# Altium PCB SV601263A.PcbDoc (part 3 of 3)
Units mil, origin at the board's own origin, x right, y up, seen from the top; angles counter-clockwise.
Board outline 4070 x 6530 mil, 6 copper layers (Top Layer, Signal Layer 1, Signal Layer 2, Signal Layer 3, Signal Layer 4, Bottom Layer), stack 60.36 mil thick; 305 components, 177 nets, 942 pads, 354 vias.
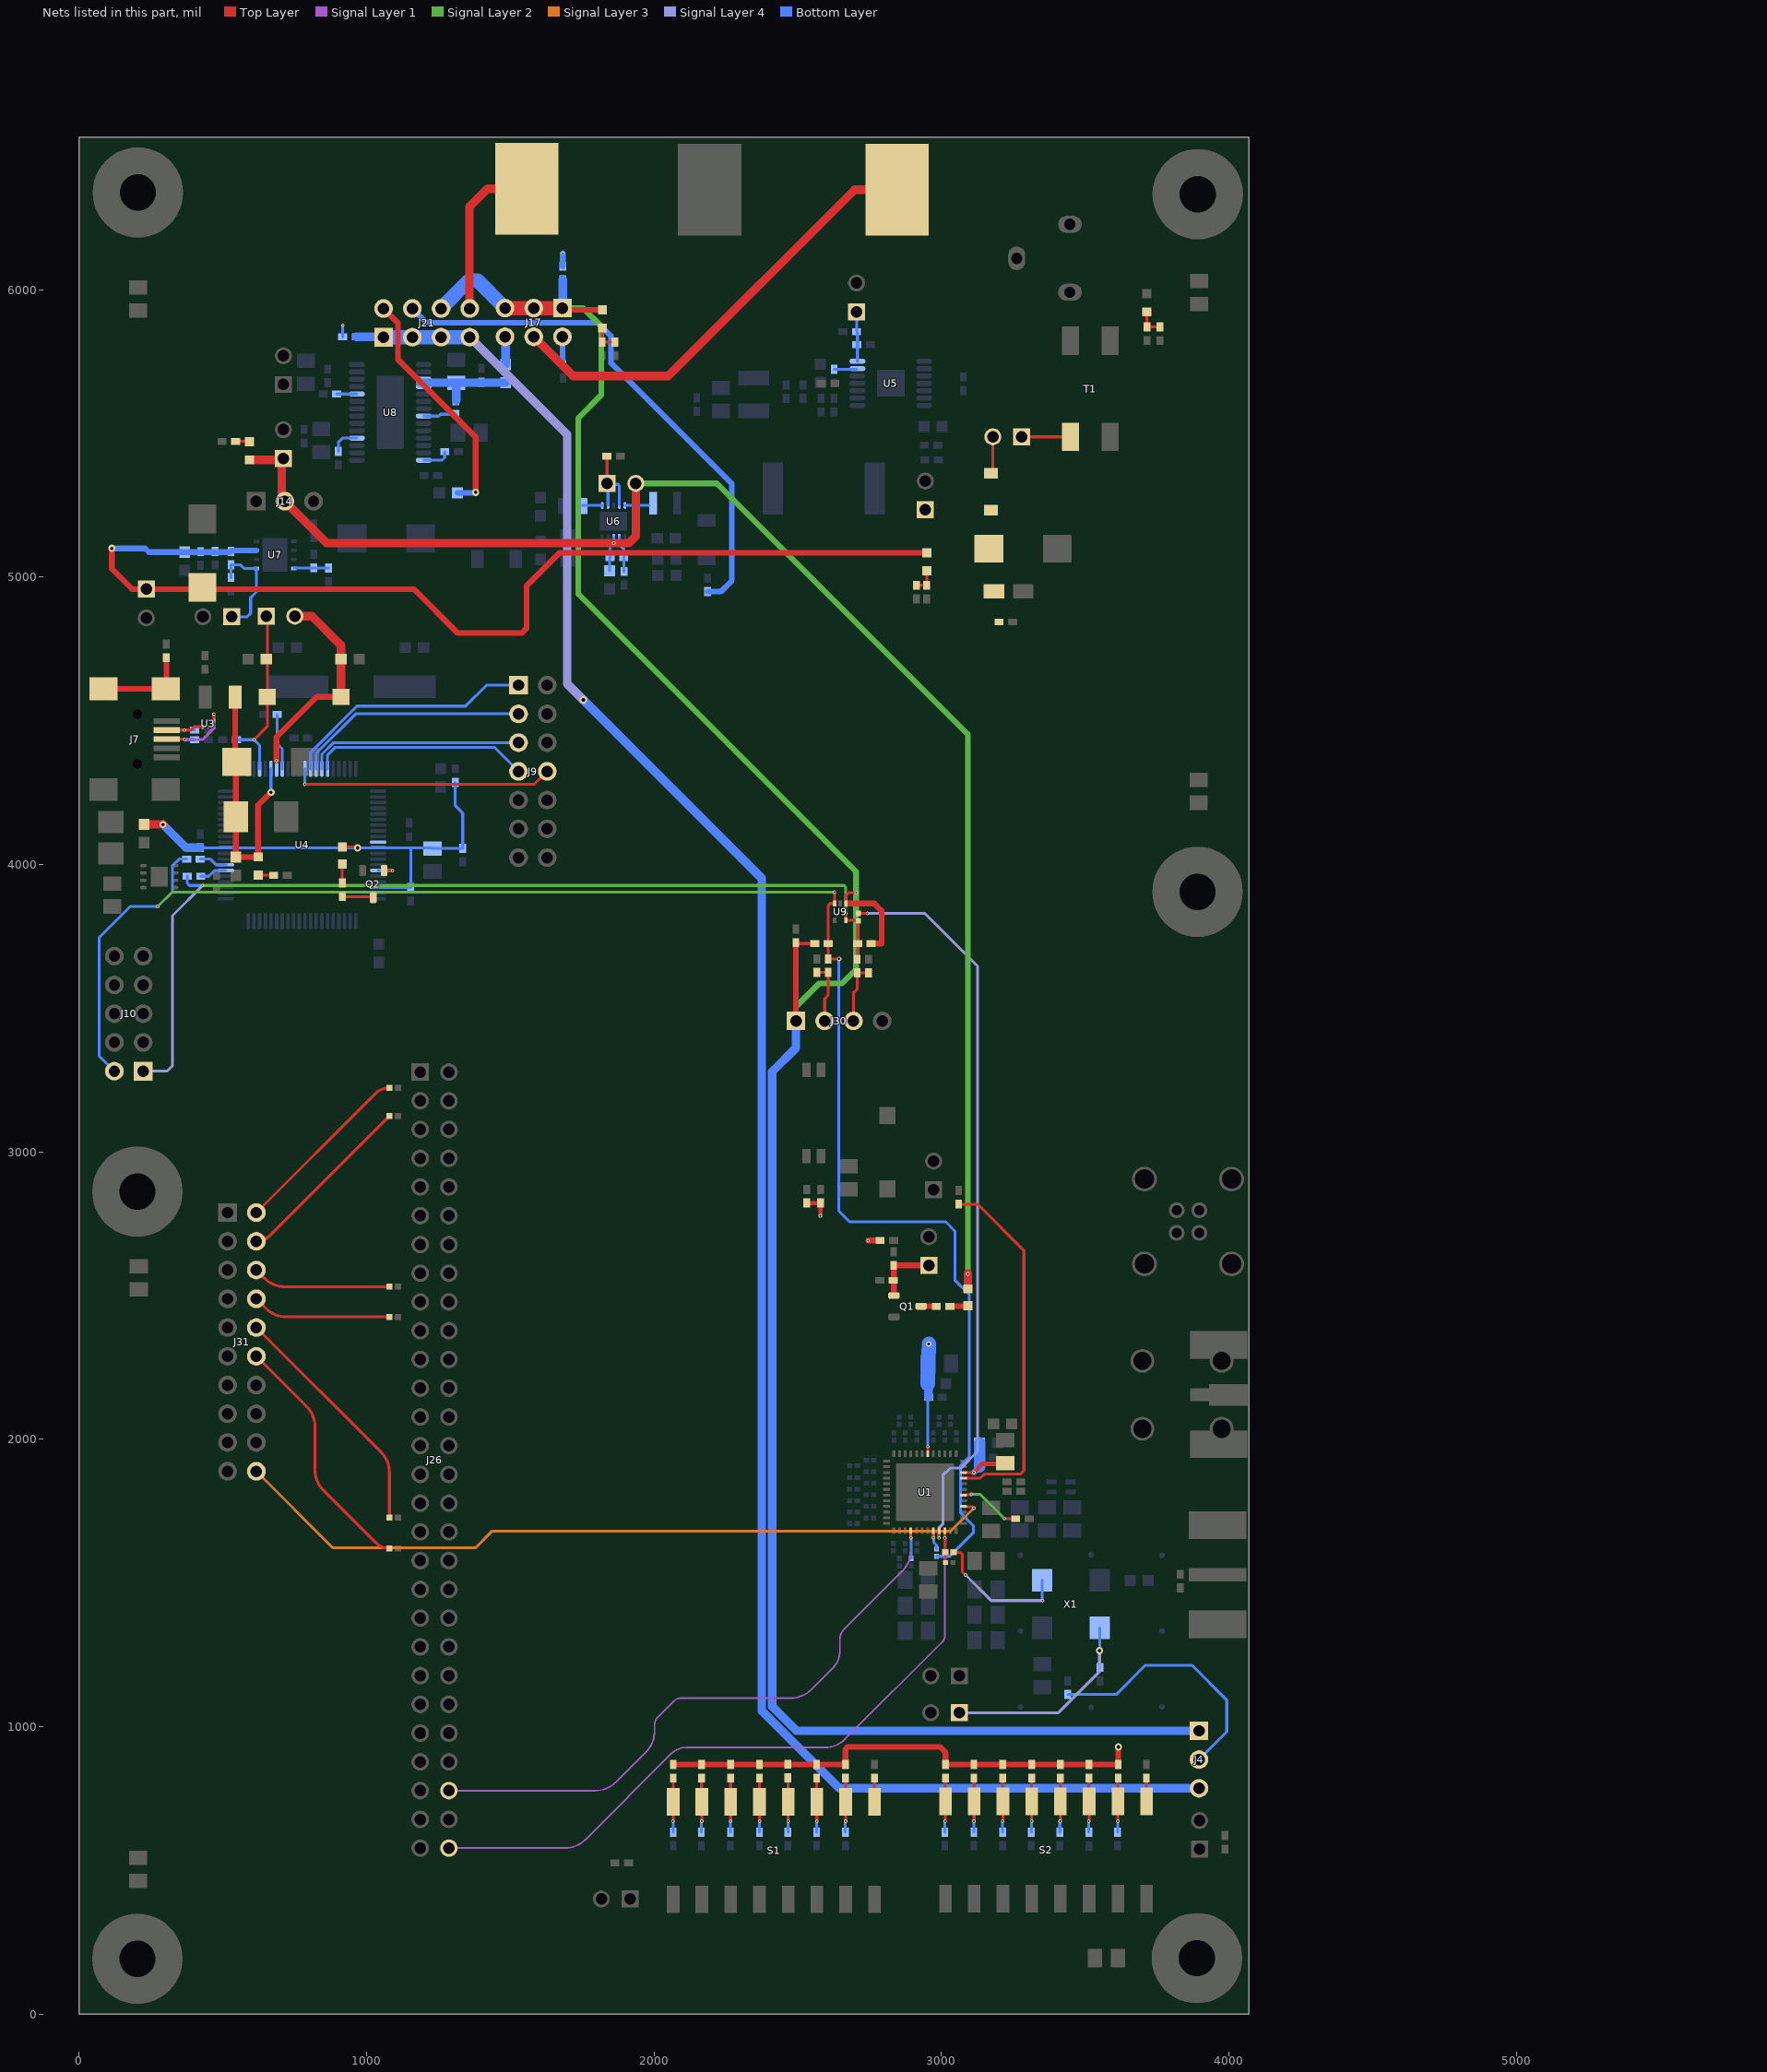
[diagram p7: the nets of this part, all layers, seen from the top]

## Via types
v1: diameter 15, hole 7.5, Top Layer to Bottom Layer, 187 vias
v2: diameter 12, hole 6, Top Layer to Bottom Layer, 96 vias
v3: diameter 19.68, hole 7.87, Top Layer to Bottom Layer, 28 vias
v4: diameter 15.75, hole 7.87, Top Layer to Bottom Layer, 18 vias
v5: diameter 20, hole 10, Top Layer to Bottom Layer, 14 vias
v6: diameter 25, hole 12, Top Layer to Bottom Layer, 9 vias
v7: diameter 16, hole 8, Top Layer to Bottom Layer, 2 vias

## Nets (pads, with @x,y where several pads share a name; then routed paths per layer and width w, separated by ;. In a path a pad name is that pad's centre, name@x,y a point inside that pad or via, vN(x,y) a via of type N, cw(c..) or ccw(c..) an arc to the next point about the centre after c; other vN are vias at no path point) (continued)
NetC78_2: C78.2 C79.1 R112.2 R114.1 U8.17 U8.18 | length 357.9
  Bottom Layer w30: 1187.5,5676.5 R114.1@1484,5676.5 ; R112.2@1312,5614.62 C79.1@1312,5676
NetC85_1: C85.1 J30.2 R118.2 | length 212.3
  Top Layer w10: C85.1@2567,3624.38 R118.2@2606,3624.38 2606,3545 2594,3533 J30.2@2594,3456
NetC86_1: C86.1 J30.3 R119.2 | length 212.8
  Top Layer w10: J30.3@2694,3456 2694,3553 2707,3566 R119.2@2707,3623.38 C86.1@2747,3623.38
NetD1_1: D1.1 R70.2 R75.2 | length 96.9
  Top Layer w10: D1.1@3715,5922.5 R75.2@3715,5870.62 R70.2@3760,5870.62
NetD2_1: D2.1 R71.2 R76.2 | length 85.9
  Top Layer w10: R76.2@2913,4971.62 R71.2@2949,4971.62 D2.1@2949,5021.5
NetD3_1: D3.1 R72.2 | length 52.9
  Top Layer w10: D3.1@623,3963.5 R72.2@675.87,3963.5
NetD4_1: D4.1 R73.2 | length 46.9
  Top Layer w10: R73.2@544.62,5472 D4.1@591.5,5472
NetD5_1: D5.1 R74.2 R77.2 | length 93.3
  Top Layer w10: D5.1@1821,5866.5 1820,5865.5 R74.2@1820,5817.62 R77.2@1864,5817.62
NetD6_2: D6.2 R69.2 | length 60.9
  Top Layer w20: R69.2@3029.62,2463 D6.2@3090.53,2463
NetD8_2: D8.2 R87.2 | length 65.9
  Top Layer w10: R87.2@916,3935.62 D8.2@916,4001.47
NetD9_2: D9.2 J12.2 | length 120.5
  Top Layer w10: D9.2@3179,5367.47 J12.2@3179,5488
NetJ4_2: J4.2 L1.2 | length 892.4
  Bottom Layer w10: L1.2@3440,1112.38 3607.38,1112.38 3709,1214 3872,1214 3993,1093 3993,983 J4.2@3896,886
NetJ6_1: J6.1 R33.1 X1.1 | length 755.9
  Signal Layer 4 w10: J6.1@3063,1049 3407,1049 3550,1192 v6(3550,1265)
  Bottom Layer w10: R33.1@3551,1207.62 X1.1@3551,1344.32
NetJ7_2: J7.2 R80.2 U3.1 | length 164.7
  Top Layer w10: J7.2@305.36,4467.5 v2(367,4467.5) 389.5,4467.5 401.17,4479.17 U3.1@430.31,4479.17
  Bottom Layer w10: v2@367.5,4468 R80.2@402.38,4468
NetJ7_3: J7.3 R81.2 U3.4 | length 281.7
  Top Layer w10: J7.3@305.36,4436 v2@367,4436 ; U3.4@469.68,4501.81 v2@469.68,4522.31
  Signal Layer 1 w10: v2(368,4435) 430,4435 469,4474 v2(469,4523)
  Bottom Layer w10: v2@369,4434 R81.2@402.38,4434
NetJ7_8: J7.8 J7.9 R83.2 | length 325.8
  Top Layer w20: J7.8@84.89,4611.2 J7.9@301.43,4611.2 304,4613.77 R83.2@304,4719.38
NetJ9_1: J9.1 U4.72 | length 877.4
  Bottom Layer w10: U4.72@805.53,4332.76 805.53,4389.53 967,4551 1345,4551 1418,4624 J9.1@1529,4624
NetJ9_3: J9.3 U4.73 | length 814.5
  Bottom Layer w10: U4.73@825.21,4332.76 825.21,4386.59 962.63,4524 J9.3@1529,4524
NetJ9_5: J9.5 U4.74 | length 751.7
  Bottom Layer w10: U4.74@844.9,4332.76 844.9,4383.64 885.25,4424 J9.5@1529,4424
NetJ9_7: J9.7 U4.75 | length 758.5
  Bottom Layer w10: U4.75@864.58,4332.76 864.58,4380.7 891.88,4408 1445,4408 J9.7@1529,4324
NetJ9_8: J9.8 U4.71 | length 915.6
  Top Layer w10: v2(785,4279) 1584,4279 J9.8@1629,4324
  Bottom Layer w10: v2@785.84,4279.84 U4.71@785.84,4332.76
NetJ12_1: J12.1 T1.3 | length 169.8
  Top Layer w10: J12.1@3279,5488 T1.3@3448.78,5488
NetJ15_1: J15.1 R93.2 R95.2 U5.7 | length 168.6
  Bottom Layer w10: R95.2@2705,5854.38 J15.1@2705,5923 ; U5.7@2707.86,5750.77 R95.2@2707.86,5850.76
NetJ16_1: J16.1 R97.2 U6.7 U6.9 | length 277.3
  Top Layer w10: J16.1@1837,5326 R97.2@1837,5419.38
  Bottom Layer w10: U6.7@1840.32,5249.12 1840.32,5322.69 1875.32,5322.69 1879.69,5318.31 U6.9@1879.69,5249.12
NetJ19_1: J19.1 R103.1 R108.2 U7.1 | length 372.1
  Bottom Layer w10: R108.2@529,4998.62 R103.1@529,5042.38 561.62,5042.38 574.24,5029.76 U7.1@617.04,5029.76 617.04,4948.04 597,4928 597,4874 585,4862 J19.1@531,4862
NetJ31_2: J31.2 R121.1 | length 639.8
  Top Layer w10: J31.2@617,2789 1030.47,3202.47 cw(c1080.04,3152.89) R121.1@1080.04,3223
NetJ31_4: J31.4 R122.1 | length 640.8
  Top Layer w10: J31.4@617,2689 ccw(c617,2754.28) 663.16,2708.12 R122.1@1080.04,3125
NetJ31_6: J31.6 R123.1 | length 482.8
  Top Layer w10: J31.6@617,2589 645.71,2560.29 ccw(c716.42,2631) 716.42,2531 R123.1@1080.04,2531
NetJ31_8: J31.8 R124.1 | length 484.8
  Top Layer w10: J31.8@617,2489 650.71,2455.29 ccw(c721.42,2526) 721.42,2426 R124.1@1080.04,2426
NetJ31_10: J31.10 R125.1 | length 848.5
  Top Layer w10: J31.10@617,2389 1050.75,1955.25 cw(c980.04,1884.54) 1080.04,1884.54 R125.1@1080.04,1728
NetJ31_12: J31.12 R126.1 | length 864.7
  Top Layer w10: J31.12@617,2289 791.71,2114.29 cw(c721,2043.58) 821,2043.58 821,1893.42 ccw(c921,1893.42) 850.29,1822.71 1032.17,1640.83 ccw(c1080.04,1688.69) R126.1@1080.04,1621
NetJ32_1: J32.1 Q1.1 R53.2 R78.2 | length 225.8
  Top Layer w20: R53.2@2834,2605.38 J32.1@2955.62,2605.38 ; Q1.1@2834.76,2500.4 R53.2@2834.76,2604.62
NetL8_1: L8.1 U6.6 | length 69.2
  Bottom Layer w10: L8.1@1751.46,5249.12 U6.6@1820.63,5249.12
NetL10_1: L10.1 U6.10 | length 83.2
  Bottom Layer w10: U6.10@1899.37,5249.12 1982.54,5249.12
NetQ1_3: Q1.3 R69.1 | length 53.1
  Top Layer w20: Q1.3@2929.24,2463 R69.1@2982.38,2463
NetQ2_1: Q2.1 U4.15 | length 77.2
  Top Layer w10: Q2.1@1061.4,3979.24 v2@1089.76,3979.24
  Bottom Layer w10: U4.15@1040.76,3979.42 v2@1089.58,3979.42
  other v2: 1091,3978
NetQ2_3: Q2.3 R87.1 | length 104.4
  Top Layer w10: R87.1@916,3888.38 Q2.3@1020.38,3888.38
NetR1_1: R1.1 R15.2 S1.16 | length 185.8
  Top Layer w10: v2@2067,673 S1.16@2067,738.29 R1.1@2067,821.38
  Bottom Layer w10: R15.2@2067,633.62 v2@2067,671
  other v2: 2066,672
NetR2_1: R2.1 R16.2 S1.15 | length 184.8
  Top Layer w10: S1.15@2166,739.29 R2.1@2166,821.38 ; v2(2167,672) S1.15@2167,738.29
  Bottom Layer w10: R16.2@2165,633.62 v2@2165,670
NetR3_1: R3.1 R17.2 S1.14 | length 188.2
  Top Layer w10: v2(2267,672) S1.14@2267,738.29 R3.1@2267,821.38
  Bottom Layer w10: v2@2266,671 R17.2@2266,633.62 R17.2@2267,634.62
NetR4_1: R4.1 R18.2 S1.13 | length 185.8
  Top Layer w10: v2@2367,673 S1.13@2367,738.29 R4.1@2367,821.38
  Bottom Layer w10: R18.2@2367,633.62 v2@2367,671
  other v2: 2368,672
NetR5_1: R5.1 R19.2 S1.12 | length 186.8
  Top Layer w10: v2(2467,672) S1.12@2467,738.29 R5.1@2467,821.38
  Bottom Layer w10: R19.2@2466,633.62 v2@2466,671
NetR6_1: R6.1 R20.2 S1.11 | length 185.8
  Top Layer w10: S1.11@2566,739.29 R6.1@2566,821.38 ; v2(2567,672) S1.11@2567,738.29
  Bottom Layer w10: R20.2@2566,633.62 v2@2566,671
NetR7_1: R7.1 R21.2 S1.10 | length 185.8
  Top Layer w10: v2(2667,672) S1.10@2667,738.29 R7.1@2667,820.38
  Bottom Layer w10: R21.2@2666,633.62 v2@2666,671
NetR8_1: R8.1 R23.2 S2.16 | length 185.8
  Top Layer w10: v2@3014,673 S2.16@3014,740.29 R8.1@3014,821.38
  Bottom Layer w10: R23.2@3012,633.62 v2@3012,671
  other v2: 3013,672
NetR9_1: R9.1 R24.2 S2.15 | length 185.8
  Top Layer w10: v2@3114,673 S2.15@3114,740.29 R9.1@3114,820.38
  Bottom Layer w10: R24.2@3113,633.62 v2(3113,672)
NetR10_1: R10.1 R25.2 S2.14 | length 185.8
  Top Layer w10: S2.14@3213,741.29 R10.1@3213,821.38 ; v2@3214,673 S2.14@3214,740.29
  Bottom Layer w10: R25.2@3213,633.62 v2(3213,672)
NetR11_1: R11.1 R26.2 S2.13 | length 186.8
  Top Layer w10: v2(3314,672) S2.13@3314,740.29 R11.1@3314,821.38
  Bottom Layer w10: R26.2@3313,633.62 v2@3313,671
NetR12_1: R12.1 R27.2 S2.12 | length 185.8
  Top Layer w10: v2@3414,673 S2.12@3414,740.29 R12.1@3414,821.38
  Bottom Layer w10: R27.2@3412,633.62 v2@3412,671
  other v2: 3413,672
NetR13_1: R13.1 R28.2 S2.11 | length 186.8
  Top Layer w10: S2.11@3513,741.29 R13.1@3513,821.38 ; v2@3514,673 S2.11@3514,740.29
  Bottom Layer w10: R28.2@3513,632.62 v2(3513,672)
NetR14_1: R14.1 R29.2 S2.10 | length 185.8
  Top Layer w10: v2(3614,672) S2.10@3614,740.29 R14.1@3614,820.38
  Bottom Layer w10: R29.2@3613,633.62 v2@3613,671
NetR22_2: R22.2 S1.9 | length 83.1
  Top Layer w10: S1.9@2767,738.29 R22.2@2767,821.38
NetR30_2: R30.2 S2.9 | length 80.1
  Top Layer w10: S2.9@3713,741.29 R30.2@3713,821.38
NetR34_1: R34.1 X1.3 | length 484
  Top Layer w10: R34.1@3042.96,1607 3066,1607 3073,1600 3073,1539 v2(3084,1528)
  Signal Layer 4 w10: v2(3084,1528) 3173,1439 v2(3352,1439)
  Bottom Layer w10: v2@3351,1440 X1.3@3351,1509.68
NetR88_2: R88.2 U4.47 | length 97.9
  Bottom Layer w10: R88.2@421.62,4019 457,4019 476.9,3999.1 U4.47@511.24,3999.1
NetR89_1: R89.1 U4.46 | length 96.1
  Bottom Layer w10: R89.1@423.62,3959 452,3959 472.42,3979.42 U4.46@511.24,3979.42
NetR92_1: R92.1 U5.6 | length 78.3
  Bottom Layer w10: R92.1@2627,5722.62 U5.6@2705.3,5722.62
NetR100_1: R100.1 R102.2 U6.2 | length 126
  Bottom Layer w10: U6.2@1879.69,5138.88 1879.69,5112.31 1896,5096 R102.2@1896,5019.62
NetR106_1: R106.1 R107.2 U7.8 | length 119.2
  Bottom Layer w10: U7.8@748.83,5031.62 R107.2@868,5031.62
NetR109_2: R109.2 U8.28 | length 96.9
  Bottom Layer w10: U8.28@1199.14,5406.66 1262.66,5406.66 1272.38,5416.38 R109.2@1272.38,5436
NetR110_2: R110.2 U8.4 | length 102.2
  Bottom Layer w10: R110.2@902,5437.62 902,5469 916.43,5483.43 U8.4@966.86,5483.43
NetR112_1: R112.1 U8.22 | length 114.4
  Bottom Layer w10: U8.22@1199.14,5560.2 1251.2,5560.2 1257.38,5566.38 R112.1@1311,5566.38
NetR113_2: R113.2 U8.10 | length 70.2
  Bottom Layer w10: R113.2@896.62,5637 U8.10@966.86,5636.98
NetU4_10: U4.10
PCLK: J26.56 R34.2 R65.1 U1.10 | length 2475.7
  Top Layer w10: v2@3011.9,1657.1 U1.10@3011.9,1682.14 ; v2@3013.04,1655.96 R34.2@3013.04,1607 3013.04,1573.34 ccw(c3016.35,1573.34) R65.1@3014.01,1571
  Signal Layer 1 w6: J26.56@1287,578 1690.58,578 ccw(c1690.58,678) 1761.29,607.29 2060,906 cw(c2113.11,852.89) 2113.11,928 2594.58,928 ccw(c2594.58,1028) 2665.29,957.29 3002,1294 ccw(c2977.86,1318.14) 3012,1318.14 v2(3012,1657)
PDB_R: R64.1 U1.21 | length 1280.7
  Top Layer w10: R64.1@3060,2818.38 3125.62,2818.38 3287,2657 3287,1891 3275,1879 3149,1879 3135.21,1865.21 U1.21@3076.86,1865.21
PUR: J8.1 R82.1 R84.2 S5.1 U4.63 | length 615.7
  Top Layer w10: v2(609,4434) 655.05,4480.05 S5.1@655.05,4583 J8.1@655.05,4859.95
  Bottom Layer w10: R82.1@547.62,4434 v2(609,4434) 628.36,4414.64 U4.63@628.36,4332.76
REM_INTB: J31.20 U1.16 | length 2702.7
  Top Layer w10: U1.16@3076.86,1766.79 3076.86,1765.47 3108.53,1765.47 v2(3113,1761)
  Signal Layer 3 w10: J31.20@617,1889 883,1623 1380,1623 1438,1681 3033,1681 v2(3113,1761)
RES1: R56.1 U1.18 | length 215.1
  Top Layer w10: U1.18@3076.86,1806.16 3076.86,1807.47 v2@3102.47,1807.47 ; v2@3220,1724 R56.1@3258.38,1724
  Signal Layer 2 w10: v2(3104,1809) 3135,1809 v2(3219,1725)
SCL: J10.2 R39.2 R88.1 R116.1 R118.1 U9.3 | length 6192.6
  Top Layer w10: R118.1@2606,3671.62 v7@2643.78,3671.62 ; R118.1@2606.62,3672.24 R116.1@2606.62,3725 2606.62,3857.62 2613.53,3864.53 U9.3@2628.32,3864.53 v2@2628.32,3903.69
  Signal Layer 2 w10: v2(274,3854) 324,3904 v2(2628,3904)
  Bottom Layer w10: J10.2@123,3281 70,3334 70,3746 178,3854 v2(274,3854) 325,3905 325,3996 348,4019 R88.1@374.38,4019 ; v7@2643,3672 2643,2795 2681,2757 3015,2757 3047,2725 3047,2554 3097,2504 3097,1940 3067,1910 3067,1744 3111,1700 3111,1675 3029.01,1593.01 R39.2@2983,1593.01
  other v7: 2644.16,3672
SCL_R: R39.1 U1.8 | length 65.8
  Top Layer w10: v2@2972.53,1658.53 U1.8@2972.53,1682.14
  Bottom Layer w10: v2@2973,1657 2973,1642 2983,1632 R39.1@2983,1618.99
  other v2: 2972,1658
SDA: J10.1 R37.2 R89.2 R115.1 R119.1 U9.5 | length 3387.6
  Top Layer w10: v2@2667.69,3829.31 U9.5@2667.69,3805.47 2704.29,3805.47 2708.38,3801.39 R115.1@2708.38,3725 R119.1@2708.38,3672
  Signal Layer 2 w10: v2(430,3927) 2661,3927 2667,3921 v2(2667,3830)
  Signal Layer 4 w10: J10.1@223,3281 306,3281 325,3300 325,3822 v2(430,3927)
  Bottom Layer w10: R89.2@376.38,3959 376.38,3934.62 384,3927 v2(430,3927)
SDA_R: R37.1 U1.9 | length 2582.9
  Top Layer w10: R37.1@2711,3829.99 v2(2743,3830) ; v2@2992.21,1657.21 U1.9@2992.21,1682.14
  Signal Layer 4 w10: v2(2743,3830) 2942,3830 3126,3646 3126,1958 3068,1900 3030,1900 3005,1875 3005,1706 2992,1693 v2(2992,1657)
V18: C22.1 U4.67 | length 196.5
  Bottom Layer w10: C22.1@689.62,4522 689.62,4420.38 707.1,4402.9 U4.67@707.1,4332.76
VBUS: C14.1 D3.2 D7.1 F1.1 L2.1 U4.65 | length 959.2
  Top Layer w20: F1.1@543.36,4583 543.36,4362.54 545.99,4359.91 D7.1@545.99,4166 L2.1@546,4025.5 D3.2@622.01,4025.5 ; D3.2@623,4026.5 623,4206 v6(668,4251)
  Bottom Layer w10: v6@667.73,4251.27 U4.65@667.73,4332.76
VDD1V8_LDO: J21.2 R111.2 | length 835.9
  Top Layer w20: J21.2@1058,5936 1109.52,5884.48 1109.52,5757.48 1380,5487 v6(1380,5295)
  Bottom Layer w20: R111.2@1316.5,5293 v6@1378,5293
VDD5V: C59.2 D4.2 D6.1 J14.2 J16.2 J22.1 R100.2 U6.3 | length 5287.7
  Top Layer w30: D4.2@593,5407.5 705.5,5407.5 J14.2@705.5,5274.5 ; J14.2@716,5264 862,5118 v2(1860,5118) 1912,5118 1937,5143 J16.2@1937,5326 ; D6.1@3092,2523.53 v2(3092,2576)
  Signal Layer 2 w20: J16.2@1937,5326 2219,5326 3092,4453 v2(3092,2576)
  Bottom Layer w10: C59.2@1846,5021.5 R100.2@1846,5065.62 ; R100.2@1847.38,5067 1847.38,5105.38 v2(1860,5118) U6.3@1860,5138.88
VDD18_SW: J21.4 R99.2 | length 1857.6
  Bottom Layer w20: J21.4@1158,5936 1209.52,5884.48 1804.52,5884.48 1851,5838 1851,5744 2271,5324 2271,4988 2232.38,4949.38 R99.2@2187,4949.38
VDD33: C83.2 D5.2 J4.1 J17.1 J17.3 J17.5 J21.6 J30.1 L7.1 R115.2 R116.2 U9.1 | length 8502.1
  Top Layer w10: C83.2@2497.38,3725 R116.2@2559.38,3725 ; U9.1@2667.69,3864.53 2667.69,3891.69 2678,3902 v2(2704,3902)
  Top Layer w20: J17.1@1688.5,5929.5 D5.2@1821,5929.5 ; J30.1@2494,3456 C83.2@2494,3728.38 ; U9.1@2669.91,3864.53 2766.47,3864.53 2792,3839 2792,3725 R115.2@2755.62,3725
  Top Layer w50: J17.5@1482,5936 J17.3@1582,5936 J17.1@1682,5936
  Signal Layer 2 w20: J17.1@1682,5936 1754,5936 1817,5873 1817,5634 1737,5554 1737,4941 2703,3975 2703,3635 2654,3586 2574,3586 2494,3506 J30.1@2494,3456
  Bottom Layer w30: J17.1@1683,5937 L7.1@1683,6034.38 ; J30.1@2494,3456 2494,3362 2411,3279 2411,1070.91 2495.91,986 J4.1@3896,986
  Bottom Layer w50: J21.6@1259.52,5934.48 1357.04,6032 1386,6032 J17.5@1482,5936
VDD33_C: C54.1 C55.1 C56.1 L7.2 R1.2 R2.2 R3.2 R4.2 R5.2 R6.2 R7.2 R8.2 R9.2 R10.2 R11.2 R12.2 R13.2 R14.2 R31.2 R32.2 U1.22 | length 2118.3
  Top Layer w10: U1.22@3076.86,1884.9 v2@3112.9,1884.9
  Top Layer w15: R32.2@2532,2822.38 R31.2@2580,2822.38 v2@2580,2779 ; v2(3113,1885) 3143,1915 3220,1915 C56.1@3222,1917
  Top Layer w20: R1.2@2067,868.62 R2.2@2166,868.62 R3.2@2267,868.62 R4.2@2367,868.62 R6.2@2566,868.62 R7.2@2666,868.62 2666,922 2674,930 2995,930 3014,911 R8.2@3014,868.62 R9.2@3113,868.62 R10.2@3213,868.62 R11.2@3314,868.62 R12.2@3414,868.62 R13.2@3513,868.62 R14.2@3615,868.62 v6@3615,929
  Bottom Layer w20: L7.2@1683,6081.62 v2(1683,6126) ; v2(3113,1885) 3131,1903
  Bottom Layer w40: 3132.5,1904.5 C55.1@3132.5,1988
  other v2: 2579,2778
  other v6: 3616,930
VDD33_EXT: J17.4 J23.1 | length 1585.9
  Top Layer w30: J17.4@1584,5834 1718,5700 2050,5700 2698,6348 J23.1@2846,6348
VDD33_LDO: J17.6 R114.2 | length 94.5
  Bottom Layer w30: R114.2@1484,5739.5 J17.6@1484,5834
VDD33_SW: J17.2 R94.2 | length 94.4
  Bottom Layer w20: R94.2@1682,5741.62 J17.2@1682,5836
VDD33_UC: C25.1 C26.1 C27.2 C28.1 D8.1 R79.2 R86.1 U4.11 U4.18 U4.50 | length 1674.6
  Top Layer w10: D8.1@916,4060.53 v6@966.63,4060.53
  Top Layer w30: R79.2@227,4139.5 v6@291.5,4139.5
  Bottom Layer w10: C25.1@422.22,4058.16 U4.50@511.24,4058.16 v6(969,4058.16) U4.11@1040.76,4058.16 C26.1@1227.84,4058.16 ; U4.18@1040.76,3920.36 C28.1@1153.74,3920.36 ; C28.1@1154,3920.62 1154,4057.16 ; C26.1@1230,4056 C27.2@1331.38,4056 ; R86.1@1309,4285.38 1309,4205 1335,4179 C27.2@1335,4056.62
  Bottom Layer w30: v6(292,4139) 372.62,4058.38 C25.1@422,4058.38
VDD_EXT: C43.2 C44.1 C45.1 C67.1 C68.1 C69.1 C70.1 D2.2 D9.1 J11.1 J18.1 R103.2 U7.3 | length 3712.5
  Top Layer w20: v6(114,5100) 114,5029 185,4958 1165,4958 1318,4805 1540,4805 1557,4822 1557,4970 1671.5,5084.5 D2.2@2949,5084.5
  Bottom Layer w20: v6(114,5100) 230.09,5100 243.6,5086.5 C68.1@368,5086.5 525.87,5086.5 R103.2@529,5089.62 532.13,5092.75 U7.3@617.04,5092.75
VDDIO: J4.3 J21.1 J21.3 J21.5 J21.7 L9.1 | length 7225.3
  Signal Layer 4 w30: J21.7@1359.52,5834.48 1698,5496 1698,4629 v6(1754,4573)
  Bottom Layer w30: L9.1@964.62,5836 J21.1@1058,5836 ; v6(1754,4573) 2375,3952 2375,1056 2645,786 J4.3@3896,786
  Bottom Layer w50: J21.1@1059.52,5834.48 J21.3@1159.52,5834.48 J21.5@1259.52,5834.48 J21.7@1359.52,5834.48
VDDIO_C: C62.1 C63.1 C64.1 L9.2 R48.2 U1.30 | length 457.7
  Top Layer w10: v2@2952.73,1975.27 v2(2953,1975) ; U1.30@2952.84,1949.86 v2@2952.84,1974.84
  Top Layer w20: v2@2746,2692 R48.2@2786.38,2692
  Bottom Layer w10: L9.2@917.38,5836 v2@917.38,5875.38 ; v2(2953,1975) 2952.73,1975.27 2952.73,2036.87 2953,2037.14 C64.1@2953,2143.62 ; C63.1@2953,2183 C63.1@2953.38,2183.38
  Bottom Layer w30: C64.1@2955.38,2146 C63.1@2955.38,2191.13
  Bottom Layer w50: C63.1@2952.5,2194 2954.28,2263.99 v5(2956,2332)
  other v2: 2745,2691 918,5876
VDDIO_EXT: J21.8 J25.1 | length 578.1
  Top Layer w30: J21.8@1358,5936 1358,6288 1421,6351 J25.1@1558,6351
VS: J26.52 R67.1 U1.4 | length 2195.2
  Top Layer w10: v2@2893.79,1658.21 U1.4@2893.79,1682.14
  Signal Layer 1 w6: J26.52@1287,778 1796.58,778 ccw(c1796.58,878) 1867.29,807.29 1972.71,912.71 ccw(c1902,983.42) 2002,983.42 2002,1008 cw(c2035.8,1008) 2011.9,1031.9 2069,1089 cw(c2095.56,1062.44) 2095.56,1100 2476.58,1100 ccw(c2476.58,1200) 2547.29,1129.29 2622,1204 ccw(c2561.64,1264.36) 2647,1264.36 2647,1305 cw(c2695.28,1305) 2661.14,1339.14 2864.71,1542.71 ccw(c2794,1613.42) 2894,1613.42 v2(2894,1658)
  Bottom Layer w10: v2(2894,1658) cw(c2891.59,1655.59) 2895,1655.59 R67.1@2895,1585.99
VUSB: C20.2 J8.2 S5.2 U4.66 | length 745.8
  Top Layer w20: v2(687,4361) 687,4443 827,4583 S5.2@910.95,4583
  Top Layer w30: J8.2@751,4864 810,4864 910.95,4763.05 S5.2@910.95,4583
pads on no net: J7.4 J7.6 J7.7 J7.10 J7.11 J9.2 J9.4 J9.6 J9.10 J9.12 J9.13 J9.14 J10.3 J10.6 LBL?.0 SH-J11.0 SH-J12.0 SH-J19.0 SH-J22.0 U2.2 U2.6 U2.7 U3.2 U3.5 U4.1 U4.2 U4.3 U4.4 U4.5 U4.6 U4.7 U4.8 U4.12 U4.13 U4.16 U4.17 U4.21 U4.22 U4.24 U4.25 U4.26 U4.27 U4.28 U4.30 U4.31 U4.32 U4.34 U4.35 U4.36 U4.37 U4.38 U4.39 U4.40 U4.41 U4.42 U4.43 U4.44 U4.45 U4.48 U4.53 U4.54 U4.55 U4.56 U4.57 U4.58 U4.59 U4.60 U4.77 U4.78 U4.79 U4.80 U7.4 U7.6 U8.1 U8.2 U8.7 U8.8 U8.13 U8.14 U8.15 U8.16 U8.19 U8.20 U8.21 U8.25 U8.26 U8.27 U9.2

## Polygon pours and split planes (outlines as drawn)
VDD33_C on Signal Layer 2 "Signal Layer 2-VDD33_C" (solid, pour order 11): 0,0 4070,0 4070,6530 0,6530
GND on Signal Layer 3 "Signal Layer 3-GND" (solid, pour order 13): 0,0 4070,0 4070,6530 0,6530
VDD_EXT on Top Layer "Top Layer-VDD_EXT" (solid, pour order 10): 2911,5265 3218,5265 3218,4833 3217,4834 2995,4834 2995,5068 2994,5069 2911,5069 2911,5265
GND on Top Layer "Top Layer-GND" (solid, remove dead copper, pour order 19): 0,0 4070,0 4070,6530 0,6530
GND on Signal Layer 1 "Signal Layer 1-GND" (solid, remove dead copper, pour order 12): 0,0 4070,0 4070,6530 0,6530
VDDIO_C on Signal Layer 4 "Signal Layer 4-VDDIO_C" (solid, remove dead copper, pour order 14): 0,0 4070,0 4070,6530 0,6530
GND on Bottom Layer "Bottom Layer-GND" (solid, remove dead copper, pour order 15): 0,0 4070,0 4070,6530 0,6530

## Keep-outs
Keep-Out Layer:
  lines w10: -5,6528 -5,0 ; 0,6528 4075,6528 4075,6 4069,0 ; 4070,-5 0,-5 ; -5,0 ccw(c0,0) 0,-5 ; -5,0 ccw(c0,0) 0,-5 ; -5,3450 cw(c0,3450) 0,3455 ccw(c0,3450) -5,3450 ; 4950,3455 cw(c4950,3450) 4955,3450 ccw(c4950,3450) 4950,3455
  text ".Layer_Name" at 577,-858.49 h60

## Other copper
Top Layer:
  text ".Layer_Name" at 577,-858.49 h60
Bottom Layer:
  pour cut-out: 3410.25,1870.59 3421.75,1870.59 3422,1870.34 3422,1865 3410,1865
  pour cut-out: 2142.5,5094.72 2225.5,5094.72 2225.5,5109.5 2226,5110 2142,5110 2142,5095.23
  pour cut-out: 2036.44,5321.37 2036.44,5192.63 2041.56,5192.63 2041.56,5321.37
  pour cut-out: 2119.18,5176.88 2236,5177.06 2236,5110.03 2127.5,5109.72 2127.5,5093.1 2121.18,5093.1 2121.18,5105.7 2119.18,5105.7
  text ".Layer_Name" at 577,-858.49 h60

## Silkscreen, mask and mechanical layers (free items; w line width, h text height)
Top Overlay:
  region: 581,1229 281,1229 281,1129 581,1129
  lines w4: 271,5023 271,5155 ; 561,4794 585,4770 873,4770 911,4808 ; 911,4808 911,5098 1067,5098 1067,4808 911,4808
  text "VDDIO EXT" at 914,6321 h60
  text "3V3 EXT" at 2322,6320 h60
  text "GND" at 1876,6307 h60
  text "1V8 SW" at 1180,6029 h60 r90
  text "1V8 LDO" at 1075,6027 h60 r90
  text "VDDIO EXT" at 1370,6024 h60 r90
  text "VDD33" at 1282,6023 h60 r90
  text "VDD33" at 1424,6019 h60
  text "GND" at 2798,6001 h60
  text "VDD3V3" at 1842,5978 h60 r90
  text "GND" at 641,5956 h60
  text "12V ADPTR" at 3810,5908 h60 r90
  text "5V SW EN" at 2801,5907 h60
  text "TPS767D318 IN MON" at 370,5841 h60
  text "VDDIO" at 1072,5679 h60
  text "3V3 SW" at 1707,5556 h60 r90
  text "3V3 LDO" at 1509,5555 h60 r90
  text "3V3 EXT" at 1607,5555 h60 r90
  text "VDD5V" at 609,5544 h60 r90
  text "TPS767D3" at 776,5495 h60
  text "VDD5" at 789,5376 h60
  text "TPS" at 2760,5318 h60
  text "LM2941 IN MON" at 34,5239 h60
  text "TPS54225 EXT" at 2510,5208 h60
  text "GND" at 175,5172 h60
  text "5V_SW" at 623,5023 h60 r90
  text "5V LDO" at 847,5021 h60 r90
  text "VDD5V" at 758,5020 h60 r90
  text "VDD EXT" at 2804,4959 h60 r90
  text "F1=F 7A H 24V" at 1217,4912 h50
  text "GND" at 968,4821 h60 r90
  text "5V REG EN" at 1029,4814 h60 r90
  text "5V USB" at 651,3593 h60 r90
  text "GND" at 2387,3331 h60 r90
  text "VDD_I2C" at 2114,3329 h60 r90
  text "SCL" at 2210,3328 h60 r90
  text "SDA" at 2297,3327 h60 r90
  text "DIN0/R0" at 1401,3258 h40
  text "DIN1/R1" at 1401,3156 h40
  text "DIN2/R2" at 1401,3052 h40
  text "DIN3/R3" at 1401,2953 h40
  text "DIN4/R4" at 1401,2852 h40
  text "DIN5/R5" at 1401,2753 h40
  text "DIN6/R6" at 1401,2653 h40
  text "DIN7/R7" at 1401,2553 h40
  text "INTB" at 3174,2475 h60 r90
  text "DIN8/G0" at 1401,2453 h40
  text "DIN9/G1" at 1401,2354 h40
  text "DIN10/G2" at 1401,2255 h40
  text "DIN11/G3" at 1401,2154 h40
  text "DOUT_P" at 3425,2147 h60
  text "DIN12/G4" at 1401,2053 h40
  text "DIN13/G5" at 1401,1952 h40
  text "DIN14/G6" at 1401,1853 h40
  text "DIN15/G7" at 1401,1753 h40
  text "DIN16/B0" at 1401,1653 h40
  text "DIN17/B1" at 1401,1553 h40
  text "DOUT_N" at 3438,1532 h60
  text "DIN18/B2" at 1401,1453 h40
  text "DIN19/B3" at 1401,1352 h40
  text ".PRJ_Number" at 275,1297 h60
  text ".PCB_Rev" at 927,1293 h60
  text "DIN20/B4" at 1401,1253 h40
  text "OSC_PWR" at 2893,1252 h60
  text "3V3" at 3875,1163 h60
  text "DIN21/B5" at 1401,1152 h40
  text "OSC_PWR" at 3782,1110 h60
  text "DIN22/B6" at 1401,1054 h40
  text "1V8" at 3891,1050 h60
  text "DIN23/B7" at 1401,955 h40
  text "OSC_EN" at 2891,928 h60
  text "HS" at 1401,853 h40
  text "VS" at 1401,753 h40
  text "IDx" at 3964,680 h60
  text "DE" at 1401,653 h40
  text "PCLK" at 1401,553 h40
  text "GND" at 3931,471 h60
  text "DS90UB921-Q1EVM" at 429,327 h80
  text "1C" at 3077,288 h40
  text "20" at 3172,288 h40
  text "24" at 3279,288 h40
  text "18" at 2979,286 h40
  text "28" at 3384,286 h40
  text "30" at 3586,286 h40
  text "2C" at 3484,285 h40
  text "34" at 3684,285 h40
  text "1" at 2059,264 h60
  text "2" at 2159,264 h60
  text "3" at 2259,264 h60
  text "4" at 2355,264 h60
  text "5" at 2466,264 h60
  text "6" at 2566,264 h60
  text "7" at 2670,264 h60
  text "8" at 2773,264 h60
  text "GND" at 1845,212 h60 r90
  text "MODE_SEL" at 2199,107 h60
  text "MODE_SEL" at 1940,59 h60 r90
  text "-" at 2430,-480 h60
  text ".Layer_Name" at 577,-858.49 h60
Bottom Overlay:
  text "DOUT0+" at 3888,2846 h60 r270
  text "DOUT0-" at 3806,2483 h60 r270
  text ".Layer_Name" at 577,-858.49 h60
Top Paste:
  text ".Layer_Name" at 577,-858.49 h60
Bottom Paste:
  text ".Layer_Name" at 577,-858.49 h60
Top Solder:
  text ".Layer_Name" at 577,-858.49 h60
  text ".Layer_Name" at 577,-858.49 h60
Bottom Solder:
  text ".Layer_Name" at 577,-858.49 h60
Drill Guide:
  text ".Layer_Name" at 577,-858.49 h60
M1 Board Outline:
  the board outline again, w10
  text ".Layer_Name" at 577,-858.49 h60
M2 Board Dimensions:
  rectangle: 125,-400 500,-275
  rectangle: 0,-275 125,-150
  lines w7: 0,-275 1000,-275 ; 125,-400 125,-150 ; 250,-400 250,-150 ; 500,-400 500,-150 ; 750,-400 750,-150 ; 0,-400 0,-150 1000,-150 1000,-400 0,-400
  text ".Layer_Name" at 577,-858.49 h60
M3 3D STEP Top:
  text ".Layer_Name" at 577,-858.49 h60
M4 3D STEP Bottom:
  text ".Layer_Name" at 577,-858.49 h60
M5 Assembly Top:
  lines w10: -292,-930.17 6308,-930.17 ; -292,-726.83 6310,-726.83 ; -292,-523.5 -292,-1133.5 3713,-1133.5 6310,-1133.5 6310,-523.5 -291.5,-523.5 -291.5,-1133.5 1284,-1133.5 ; 2173,-1133.5 2173,-523.5 ; 3440,-726.83 3440,-523.5 ; 4280,-726.83 4280,-523.5 ; 4902,-1140 4902,-937.17
  text "COMPONENTS MARKED 'DNP' SHOULD NOT BE POPULATED." at 1153.5,-318.5 h60
  text "ASSEMBLY VARIANT:" at 1153,-434 h60
  text ".VariantName" at 2189,-434 h60
  text "PCB VIEWED FROM TOP SIDE" at -228.5,-655.67 h60
  text "BOARD #:" at 2248,-655.67 h60
  text ".PRJ_Number" at 2793.5,-655.67 h60
  text "REV:" at 3638,-655.67 h60
  text ".PCB_Rev" at 3929.5,-655.67 h60
  text "SVN REV:" at 4476,-655.67 h60
  text ".VersionControl_RevNumber" at 4982,-655.67 h60
  text "TID #:" at 2248,-859 h60
  text ".TID" at 2793.5,-859 h60
  text "PLOT NAME =" at -228.5,-1064.34 h60
  text ".plot_File_Name" at 577,-1064.34 h60
  text "GENERATED    :" at 2250,-1064.34 h60
  text ".Print_Date" at 3119.5,-1064.34 h60
  text ".Print_Time" at 3848.5,-1064.34 h60
  text "TEXAS INSTRUMENTS" at 5113,-1064.34 h60
M6 Assembly Bottom:
  lines w10: -292.5,-727.33 6309.5,-727.33 ; -290.5,-930.67 6309.5,-930.67 ; 1115.5,-1140.5 1115.5,-937.67 ; 1737.5,-727.33 1737.5,-524 ; 2577.5,-727.33 2577.5,-524 ; 3844.5,-1134 3844.5,-524 ; 4733.5,-1134 6309,-1134 6309,-524 -292.5,-524 -292.5,-1134 2304.5,-1134 6309.5,-1134 6309.5,-524
  text "COMPONENTS MARKED 'DNP' SHOULD NOT BE POPULATED." at 6102,-318 h60
  text ".VariantName" at 5058,-434 h60
  text "ASSEMBLY VARIANT:" at 6097,-434 h60
  text ".VersionControl_RevNumber" at 1035.5,-656.17 h60
  text "SVN REV:" at 1541.5,-656.17 h60
  text ".PCB_Rev" at 2088,-656.17 h60
  text "REV:" at 2379.5,-656.17 h60
  text ".PRJ_Number" at 3224,-656.17 h60
  text "BOARD #:" at 3769.5,-656.17 h60
  text "PCB VIEWED FROM BOTTOM SIDE" at 6246,-656.17 h60
  text ".TID" at 3224,-859.5 h60
  text "TID #:" at 3769.5,-859.5 h60
  text "TEXAS INSTRUMENTS" at 904.5,-1064.84 h60
  text ".Print_Time" at 2169,-1064.84 h60
  text ".Print_Date" at 2898,-1064.84 h60
  text "GENERATED    :" at 3767.5,-1064.84 h60
  text ".plot_File_Name" at 5440.5,-1064.84 h60
  text "PLOT NAME =" at 6246,-1064.84 h60
M9 Title Sheet:
  drawing of 57 lines, arcs and shapes, not listed
  text "1" at 739.84,8036.5 h70
  text "2" at 3235.5,8036.5 h70
  text "3" at 5724.84,8036.5 h70
  text "4" at 8231.51,8036.5 h70
  text "5" at 10730.5,8036.5 h70
  text "6" at 13235.5,8036.5 h70
  text "A" at -416.5,6893.5 h70
  text "A" at 14383.5,6893.5 h70
  text "B" at -416.5,4513.5 h70
  text "B" at 14383.5,4513.5 h70
  text "C" at -416.5,2138.5 h70
  text "C" at 14383.5,2138.5 h70
  text "PROJECT TITLE:" at 11343.5,277.5 h45
  text ".PRJ_Title" at 11393.5,144.17 h70
  text "DESIGNED FOR:" at 11343.5,-23.5 h45
  text ".PRJ_Customer" at 11393.5,-163.5 h70
  text "D" at -416.5,-231.5 h70
  text "D" at 14383.5,-231.5 h70
  text "FILE NAME:" at 11343.5,-323.5 h45
  text ".PCB_File_Name_No_Path" at 11393.5,-443.5 h70
  text "Texas Instruments (TI) and/or its licensors do not warrant the accuracy or completeness of this specification" at 6374,-605.34 h45
  text "ENGINEER:" at 11343.5,-613.5 h45
  text "LAYOUT BY:" at 12848.5,-613.5 h45
  text "or any information contained therein. TI and/or its licensors do not warrant that this design will meet" at 6329.01,-718 h45
  text ".PRJ_Engineer" at 11393.5,-768.49 h70
  text ".PCB_Layout" at 12899,-768.49 h70
  text "the specifications, will be suitable for your application or fit for any particular purpose, or will operate in" at 6329.01,-830.67 h45
  text ".Layer_Name" at 577,-858.49 h60
  text "ALTIUM DESIGNER VERSION:" at 12848.5,-923.5 h45
  text "an implementation. TI and/or its licensors do not warrant that the design is production worthy. You should" at 6329.01,-943.33 h45
  text "completely validate and test your design implementation to confirm the system functionality for your application." at 6374,-1056 h45
  text ".print_Scale" at 11393.5,-1056.83 h70
  text ".Application_BuildNumber" at 12899,-1056.83 h70
  text "1" at 739.84,-1263.5 h70
  text "2" at 3235.5,-1263.5 h70
  text "3" at 5724.84,-1263.5 h70
  text "4" at 8231.51,-1263.5 h70
  text "5" at 10730.5,-1263.5 h70
  text "6" at 13235.5,-1263.5 h70
M10 Fab Notes:
  drawing of 173 lines, arcs and shapes, not listed
  text "DESIGN INFORMATION" at 12377.02,6201 h60
  text "MIN. TRACK WIDTH:" at 11732.46,6021 h60
  text "8" at 12828.7,6021 h60
  text "MIL" at 12983.46,6021 h60
  text "MIN. CLEARANCE:" at 11732.46,5889 h60
  text "0.2" at 12768.7,5889 h60
  text "mm" at 12983.46,5889 h60
  text "MIN. VIA PAD SIZE:" at 11732.46,5757 h60
  text "24" at 12798.71,5757 h60
  text "MIL" at 12983.46,5757 h60
  text "0.05mm (2MIL)" at 12427.46,5615.29 h60
  text "MINIMUM ANNULAR RING" at 11403.23,5611 h60
  text "EXTERNAL" at 13135.46,5611 h60
  text "PER" at 11603.23,5493 h60
  text "IPC-D-275 CLASS 2 LEVEL C" at 11823.23,5493 h60
  text "MIL, HOLES" at 13311.46,5380.71 h60
  text "+/-" at 12919,5380 h60
  text "+/-" at 13773,5380 h60
  text "REGISTRATION TOLERANCES:" at 11403.23,5375 h60
  text "METAL" at 12603,5375 h60
  text "5" at 13179.2,5375 h60
  text "3" at 14012.2,5375 h60
  text "MIL" at 14128.46,5375 h60
  text "+/-" at 13773,5262 h60
  text "HOLE SIZE TOLERANCE (UNLESS OTHERWISE SPECIFIED):" at 11403.23,5257 h60
  text "3" at 14012.2,5257 h60
  text "MIL" at 14128.46,5257 h60
  text "MATERIAL:" at 11328.46,5047.54 h60
  text "FR-4 High Tg" at 12314.9,4907.21 h60
  text "FR-408" at 11749.46,4898.64 h60
  text "OTHER" at 13237.46,4898.64 h60
  text "X" at 12160,4895 h60
  text "62 MIL (1.6mm) +/-10%" at 12069.56,4735.92 h60
  text "THICKNESS:" at 11403.23,4731.64 h60
  text "X" at 11941.4,4731.64 h60
  text "OTHER" at 13354.46,4731.64 h60
  text "TOLERANCE:" at 11403.23,4573.64 h60
  text "X" at 12242.53,4573.64 h60
  text "ANSI IPC-6012 TYPE 3 CLASS 2" at 12429.48,4573.64 h60
  text "OTHER +/-" at 12429.46,4417.64 h60
  text "BOW & TWIST:" at 11403.23,4260.64 h60
  text "X" at 12242.53,4260.64 h60
  text "ANSI IPC-6012 TYPE 3 CLASS 2" at 12429.48,4260.64 h60
  text "OTHER +/-" at 12429.46,4102.13 h60
  text "DRILLING:" at 11328.46,3963.64 h60
  text "REFERENCE:" at 11403.23,3846.64 h60
  text "X" at 12051.46,3846.64 h60
  text "AS SHOWN" at 12238.46,3846.64 h60
  text "X" at 12952.46,3846.64 h60
  text "NC_DRILL FILES" at 13089.46,3846.64 h60
  text "PTH MIN COPPER THICKNESS:" at 11403.23,3688.64 h60
  text "X" at 12753.46,3688.64 h60
  text "1MIL" at 12890.46,3688.64 h60
  text "OTHER" at 13387.46,3688.64 h60
  text "BOARD FINISH:" at 11328.46,3529.64 h60
  text "SILKSCREEN:" at 11483.68,3411.64 h60
  text "X" at 12432.46,3411.64 h60
  text "TOP" at 12558.46,3411.64 h60
  text "X" at 12942.46,3411.64 h60
  text "BOTTOM" at 13069.46,3411.64 h60
  text "SILKSCREEN COLOR:" at 11483.68,3244.64 h60
  text "X" at 12431.42,3244.64 h60
  text "WHITE" at 12558.46,3244.64 h60
  text "OTHER" at 13069.46,3244.64 h60
  text "FAB NOTES:" at 5584,3187 h150
  text "X" at 12562.42,3085.44 h60
  text "GREEN" at 12689.46,3085.44 h60
  text "OTHER" at 13307.46,3085.44 h60
  text "SOLDER RESIST COLOR:" at 11483.68,3074.64 h60
  text "BOARD SHOULD BE PANELIZED WITH .500 RAILSON BOTH SIDES." at 5752,2938 h150
  text "X" at 12562.42,2915.44 h60
  text "MATTE" at 12689.46,2915.44 h60
  text "SEMI-GLOSS" at 13307,2914.8 h60
  text "ALL 6.0 MIL DRILL NEEDS TO BE CONDUCTIVE FILLED AND PLATED OVER TOP." at 5752,2740 h150
  text "IMMERSION GOLD (ENIG)" at 12389.46,2726.92 h60
  text "ENEPIG" at 13727,2723.64 h60
  text "SURFACE FINISH:" at 11328.46,2722.64 h60
  text "X" at 12202.51,2722.64 h60
  text "IMM. TIN/SILVER OR EQUIV" at 11658,2565.64 h60
  text "OTHER" at 13089.46,2565.64 h60
  text "ALL VIAS SHOULD BE TENTED (TOP AND BOTTOM)" at 5752,2543 h150
  text "IMPEDANCE DETAILS:" at 5752,2394 h150
  text "ARRAY/PANEL:" at 11328.46,2386.64 h60
  text "CUT AND TRIM PER M1 BOARD OUTLINE" at 12389.46,2382.35 h60
  text "DIFFERENTIAL PAIRS REQUIRE 100 OHM DIFFERENTIAL IMPEDANCE" at 5752,2260 h150
  text "N.C. ROUTE" at 12389.46,2230.64 h60
  text "X" at 13068.46,2230.64 h60
  text "V. SCORE" at 13255.46,2230.64 h60
  text "All 5.5 mil and 4.5 mil traces are differential 100 ohm impedance matched with +/- 5% tolerance." at 5752,2102 h150
  text "CERTIFICATION:" at 11328.46,2093.64 h60
  text "MATERIALS AND WORKMANSHIP FOR ALL PCBS" at 12053.46,2093.64 h60
  text "TO MEET OR EXCEED THE REQUIREMENTS OF:" at 12053.46,1995.64 h60
  text "All 9 mil and 4 mil traces are 50 ohm single ended impedance with +/- 5% tolerance" at 5752,1977 h150
  text "X" at 11679.96,1859.13 h60
  text "ANSI IPC-A-600F CLASS ->" at 11818.96,1859.13 h60
  text "X" at 13458.02,1859.13 h60
  text "2" at 13576.96,1859.14 h60
  text "1" at 13261.96,1857.64 h60
  text "3" at 13930.96,1857.64 h60
  text "BOARD THICKNESS : 62 MILS +/- 10%" at 5752,1703 h150
  text "X" at 12494.02,1699.64 h60
  text "RoHS" at 12630.96,1699.64 h60
  text "OTHER" at 13275.36,1699.64 h60
  text "PER ORDER" at 13672.42,1699.64 h60
  text "DIELECTRIC : FR4" at 5752,1569 h150
  text "ALL BOARDS MUST MEET OR EXCEED UL94-V0 REQUIREMENTS." at 11356,1534 h60
  text "NUMBER OF LAYERS: 6." at 5752,1448 h150
  text "PCB MUST BEAR THE UL94V-0 UL REGISTERED MATERIAL ID NUMBER" at 11356,1414 h60
  text "SOLDERMASK : LPI GREEN." at 5752,1316 h150
  text "ADDITIONAL REQUIREMENTS:" at 11328.46,1240.64 h60
  text "SILKSCREEN : WHITE EPOXY INK." at 5752,1199 h150
  text "MICROSECTION:" at 11403.23,1125.64 h60
  text "YES" at 12308.96,1125.64 h60
  text "NO VENDOR LOGO OR NAME ON THE BOARD." at 5752,1077 h150
  text "REQUIRED" at 13170.46,969.49 h60
  text "BARE BOARD ELEC. TEST:" at 11403.23,966.64 h60
  text "NONE" at 12708.96,966.64 h60
  text "X" at 13043.46,966.64 h60
  text "PER ORDER" at 13762.46,966.64 h60
  text "REMOVE THE NON-FUNCTIONAL PADS ON ALL INNER LAYERS." at 5752,954 h150
  text "MAXIMUM WARP AND TWIST SHALL NOT EXCEED .005 PER INCH." at 5752,826 h150
  text "DEBURR ALL SHARP EDGES." at 5752,709 h150
  text "BOARD DIMENSIONS ARE IN MILS" at 5752,598 h150
  text "THIS BOARD SHOULD BE LEAD FREE." at 5757,472.3 h150
  text "CLIP SILKSCREEN ON NO MASK AREAS." at 5757,353.3 h150
  text ".Layer_Name" at 577,-858.49 h60
M11 Gerber Information:
  lines w10: -292,-930.17 6308,-930.17 ; -292,-726.83 6310,-726.83 ; -292,-523.5 -292,-1133.5 3713,-1133.5 6310,-1133.5 6310,-523.5 -291.5,-523.5 -291.5,-1133.5 1284,-1133.5 ; 2173,-1133.5 2173,-523.5 ; 3440,-726.83 3440,-523.5 ; 4280,-726.83 4280,-523.5 ; 4902,-1140 4902,-937.17
  text "ALL ARTWORK VIEWED FROM TOP SIDE" at -228.5,-655.67 h60
  text "BOARD #:" at 2248,-655.67 h60
  text ".PRJ_Number" at 2793.5,-655.67 h60
  text "REV:" at 3638,-655.67 h60
  text ".PCB_Rev" at 3929.5,-655.67 h60
  text "SVN REV:" at 4476,-655.67 h60
  text ".VersionControl_RevNumber" at 4982,-655.67 h60
  text "LAYER NAME =" at -228.5,-858.49 h60
  text "TID #:" at 2248,-859 h60
  text ".TID" at 2793.5,-859 h60
  text "PLOT NAME =" at -228.5,-1064.34 h60
  text ".plot_File_Name" at 577,-1064.34 h60
  text "GENERATED    :" at 2250,-1064.34 h60
  text ".Print_Date" at 3119.5,-1064.34 h60
  text ".Print_Time" at 3848.5,-1064.34 h60
  text "TEXAS INSTRUMENTS" at 5113,-1064.34 h60
M12 Stackup:
  drawing of 399 lines, arcs and shapes, not listed
  text "Layer" at 6791,7844 h60
  text "Name" at 7200.91,7844 h60
  text "Material" at 8140.65,7844 h60
  text "Thickness" at 9000.42,7844 h60
  text "Constant" at 9650.26,7844 h60
  text "Board Layer Stack" at 10220.12,7844 h60
  text "1" at 6791,7724 h60
  text "Top Overlay" at 7200.91,7724 h60
  text "2" at 6791,7604 h60
  text "Top Solder" at 7200.91,7604 h60
  text "Solder Resist" at 8140.65,7604 h60
  text "0.70mil" at 9000.42,7604 h60
  text "3.5" at 9650.26,7604 h60
  text "3" at 6791,7484 h60
  text "Top Layer" at 7200.91,7484 h60
  text "Copper" at 8140.65,7484 h60
  text "1.58mil" at 9000.42,7484 h60
  text "4" at 6791,7364 h60
  text "Dielectric1" at 7200.91,7364 h60
  text "FR-4" at 8140.65,7364 h60
  text "5.00mil" at 9000.42,7364 h60
  text "4.2" at 9650.26,7364 h60
  text "5" at 6791,7244 h60
  text "Signal Layer 1" at 7200.91,7244 h60
  text "Copper" at 8140.65,7244 h60
  text "1.30mil" at 9000.42,7244 h60
  text "6" at 6791,7124 h60
  text "Dielectric 3" at 7200.91,7124 h60
  text "6.00mil" at 9000.42,7124 h60
  text "4.2" at 9650.26,7124 h60
  text "7" at 6791,7004 h60
  text "Signal Layer 2" at 7200.91,7004 h60
  text "Copper" at 8140.65,7004 h60
  text "1.30mil" at 9000.42,7004 h60
  text "8" at 6791,6884 h60
  text "Dielectric 4" at 7200.91,6884 h60
  text "30.00mil" at 9000.42,6884 h60
  text "4.2" at 9650.26,6884 h60
  text "9" at 6791,6764 h60
  text "Signal Layer 3" at 7200.91,6764 h60
  text "Copper" at 8140.65,6764 h60
  text "1.30mil" at 9000.42,6764 h60
  text "10" at 6791,6644 h60
  text "Dielectric 5" at 7200.91,6644 h60
  text "6.00mil" at 9000.42,6644 h60
  text "4.2" at 9650.26,6644 h60
  text "11" at 6791,6524 h60
  text "Signal Layer 4" at 7200.91,6524 h60
  text "Copper" at 8140.65,6524 h60
  text "1.30mil" at 9000.42,6524 h60
  text "12" at 6791,6404 h60
  text "Dielectric 2" at 7200.91,6404 h60
  text "5.00mil" at 9000.42,6404 h60
  text "4.2" at 9650.26,6404 h60
  text "13" at 6791,6284 h60
  text "Bottom Layer" at 7200.91,6284 h60
  text "Copper" at 8140.65,6284 h60
  text "1.58mil" at 9000.42,6284 h60
  text "14" at 6791,6164 h60
  text "Bottom Solder" at 7200.91,6164 h60
  text "Solder Resist" at 8140.65,6164 h60
  text "0.70mil" at 9000.42,6164 h60
  text "3.5" at 9650.26,6164 h60
  text "15" at 6791,6044 h60
  text "Bottom Overlay" at 7200.91,6044 h60
  text ".Layer_Name" at 577,-858.49 h60
M13 Component Bodies Top:
  text ".Layer_Name" at 577,-858.49 h60
M14 Component Bodies Bottom:
  text ".Layer_Name" at 577,-858.49 h60
M15 Courtyards Top:
  text ".Layer_Name" at 577,-858.49 h60
M16 Courtyards Bottom:
  text ".Layer_Name" at 577,-858.49 h60
Drill Drawing:
  lines w10: 6174.5,4788.49 6187.24,4788.49 6187.24,4775.76 6212.71,4775.76 6212.71,4788.49 6225.45,4788.49 6225.45,4813.97 6212.71,4813.97 6212.71,4826.7 6187.24,4826.7 6187.24,4813.97 6174.5,4813.97 6174.5,4788.49 ; 6184.69,4793.59 6192.33,4793.59 6192.33,4785.95 6207.62,4785.95 6207.62,4793.59 6215.26,4793.59 6215.26,4808.87 6207.62,4808.87 6207.62,4816.51 6192.33,4816.51 6192.33,4808.87 6184.69,4808.87 6184.69,4793.59
  lines w15: 6128.07,3938.98 10945.05,3938.98 ; 6128.07,5543.76 10945.05,5543.76 ; 6556.59,3824.35 6556.59,5658.39 ; 7097.4,3824.35 7097.4,5658.39 ; 8133.23,3824.35 8133.23,5658.39 ; 8527.36,3824.35 8527.36,5658.39 ; 9095.67,3824.35 9095.67,5658.39 ; 9975.66,3824.35 9975.66,5658.39 ; 6128.07,3824.35 10945.05,3824.35 10945.05,5658.39 6128.07,5658.39 6128.07,3824.35
  text "Symbol" at 6196.85,5578.15 h55.02
  text "Hit Count" at 6590.98,5578.15 h55.02
  text "Finished Hole Size" at 7131.78,5578.15 h55.02
  text "Plated" at 8167.62,5578.15 h55.02
  text "Hole Type" at 8561.75,5578.15 h55.02
  text "Physical Length" at 9130.06,5578.15 h55.02
  text "Rout Path Length" at 10010.05,5578.15 h55.02
  text "2" at 6590.98,5463.52 h45.85
  text "8.00mil (0.203mm)" at 7131.78,5463.52 h45.85
  text "PTH" at 8167.62,5463.52 h45.85
  text "Round" at 8561.75,5463.52 h45.85
  text "-" at 9130.06,5463.52 h45.85
  text "-" at 10010.05,5463.52 h45.85
  text "L" at 6173,5453.53 h50.95
  text "2" at 6590.98,5348.9 h45.85
  text "35.43mil (0.900mm)" at 7131.78,5348.9 h45.85
  text "NPTH" at 8167.62,5348.9 h45.85
  text "Round" at 8561.75,5348.9 h45.85
  text "-" at 9130.06,5348.9 h45.85
  text "-" at 10010.05,5348.9 h45.85
  text "F" at 6173,5338.9 h50.95
  text "3" at 6590.98,5234.27 h45.85
  text "39.37mil (1.000mm)" at 7131.78,5234.27 h45.85
  text "PTH" at 8167.62,5234.27 h45.85
  text "Slot" at 8561.75,5234.27 h45.85
  text "62.99mil (1.600mm)" at 9130.06,5234.27 h45.85
  text "23.62mil (0.600mm)" at 10010.05,5234.27 h45.85
  text "G" at 6173,5224.28 h50.95
  text "4" at 6590.98,5119.64 h45.85
  text "35.43mil (0.900mm)" at 7131.78,5119.64 h45.85
  text "PTH" at 8167.62,5119.64 h45.85
  text "Round" at 8561.75,5119.64 h45.85
  text "-" at 9130.06,5119.64 h45.85
  text "-" at 10010.05,5119.64 h45.85
  text "D" at 6173,5109.65 h50.95
  text "4" at 6590.98,5005.01 h45.85
  text "62.99mil (1.600mm)" at 7131.78,5005.01 h45.85
  text "PTH" at 8167.62,5005.01 h45.85
  text "Round" at 8561.75,5005.01 h45.85
  text "-" at 9130.06,5005.01 h45.85
  text "-" at 10010.05,5005.01 h45.85
  text "C" at 6173,4995.02 h50.95
  text "4" at 6590.98,4890.39 h45.85
  text "66.93mil (1.700mm)" at 7131.78,4890.39 h45.85
  text "PTH" at 8167.62,4890.39 h45.85
  text "Round" at 8561.75,4890.39 h45.85
  text "-" at 9130.06,4890.39 h45.85
  text "-" at 10010.05,4890.39 h45.85
  text "E" at 6173,4880.39 h50.95
  text "6" at 6590.98,4775.76 h45.85
  text "125.98mil (3.200mm)" at 7131.78,4775.76 h45.85
  text "PTH" at 8167.62,4775.76 h45.85
  text "Round" at 8561.75,4775.76 h45.85
  text "-" at 9130.06,4775.76 h45.85
  text "-" at 10010.05,4775.76 h45.85
  text "9" at 6590.98,4661.13 h45.85
  text "12.00mil (0.305mm)" at 7131.78,4661.13 h45.85
  text "PTH" at 8167.62,4661.13 h45.85
  text "Round" at 8561.75,4661.13 h45.85
  text "-" at 9130.06,4661.13 h45.85
  text "-" at 10010.05,4661.13 h45.85
  text "J" at 6173,4651.14 h50.95
  text "14" at 6590.98,4546.5 h45.85
  text "10.00mil (0.254mm)" at 7131.78,4546.5 h45.85
  text "PTH" at 8167.62,4546.5 h45.85
  text "Round" at 8561.75,4546.5 h45.85
  text "-" at 9130.06,4546.5 h45.85
  text "-" at 10010.05,4546.5 h45.85
  text "I" at 6181.49,4536.51 h50.95
  text "46" at 6590.98,4431.87 h45.85
  text "7.87mil (0.200mm)" at 7131.78,4431.87 h45.85
  text "PTH" at 8167.62,4431.87 h45.85
  text "Round" at 8561.75,4431.87 h45.85
  text "-" at 9130.06,4431.87 h45.85
  text "-" at 10010.05,4431.87 h45.85
  text "K" at 6173,4421.88 h50.95
  text "68" at 6590.98,4317.25 h45.85
  text "40.00mil (1.016mm)" at 7131.78,4317.25 h45.85
  text "PTH" at 8167.62,4317.25 h45.85
  text "Round" at 8561.75,4317.25 h45.85
  text "-" at 9130.06,4317.25 h45.85
  text "-" at 10010.05,4317.25 h45.85
  text "B" at 6173,4307.26 h50.95
  text "86" at 6590.98,4202.62 h45.85
  text "40.16mil (1.020mm)" at 7131.78,4202.62 h45.85
  text "PTH" at 8167.62,4202.62 h45.85
  text "Round" at 8561.75,4202.62 h45.85
  text "-" at 9130.06,4202.62 h45.85
  text "-" at 10010.05,4202.62 h45.85
  text "A" at 6173,4192.63 h50.95
  text "96" at 6590.98,4087.99 h45.85
  text "6.00mil (0.152mm)" at 7131.78,4087.99 h45.85
  text "PTH" at 8167.62,4087.99 h45.85
  text "Round" at 8561.75,4087.99 h45.85
  text "-" at 9130.06,4087.99 h45.85
  text "-" at 10010.05,4087.99 h45.85
  text "H" at 6173,4078 h50.95
  text "187" at 6590.98,3973.36 h45.85
  text "7.50mil (0.191mm)" at 7131.78,3973.36 h45.85
  text "PTH" at 8167.62,3973.36 h45.85
  text "Round" at 8561.75,3973.36 h45.85
  text "-" at 9130.06,3973.36 h45.85
  text "-" at 10010.05,3973.36 h45.85
  text "M" at 6173,3963.37 h50.95
  text "531 Total" at 6590.98,3858.74 h45.85
  text "Slot definitions :" at 6196.85,3743.23 h45.85
  text "Rout Path Length" at 6992.62,3743.23 h45.85
  text "= Calculated from tool start centre position to tool end centre position." at 7750.19,3743.23 h45.85
  text "Physical Length" at 6992.62,3662.12 h45.85
  text "= Rout Path Length + Tool Size = Slot length as defined in the PCB layout" at 7704.36,3662.12 h45.85
  text ".Layer_Name" at 577,-858.49 h60

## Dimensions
0,0 to 4070,0 on M2 Board Dimensions
0,0 to 0,6530 on M2 Board Dimensions
0,-400 to 1000,-400 on M2 Board Dimensions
